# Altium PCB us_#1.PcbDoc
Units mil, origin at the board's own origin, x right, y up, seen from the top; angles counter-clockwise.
Board outline 1397.64 x 1968.5 mil, 2 copper layers (Top Layer, Bottom Layer); 23 components, 13 nets, 121 pads, 6 vias.
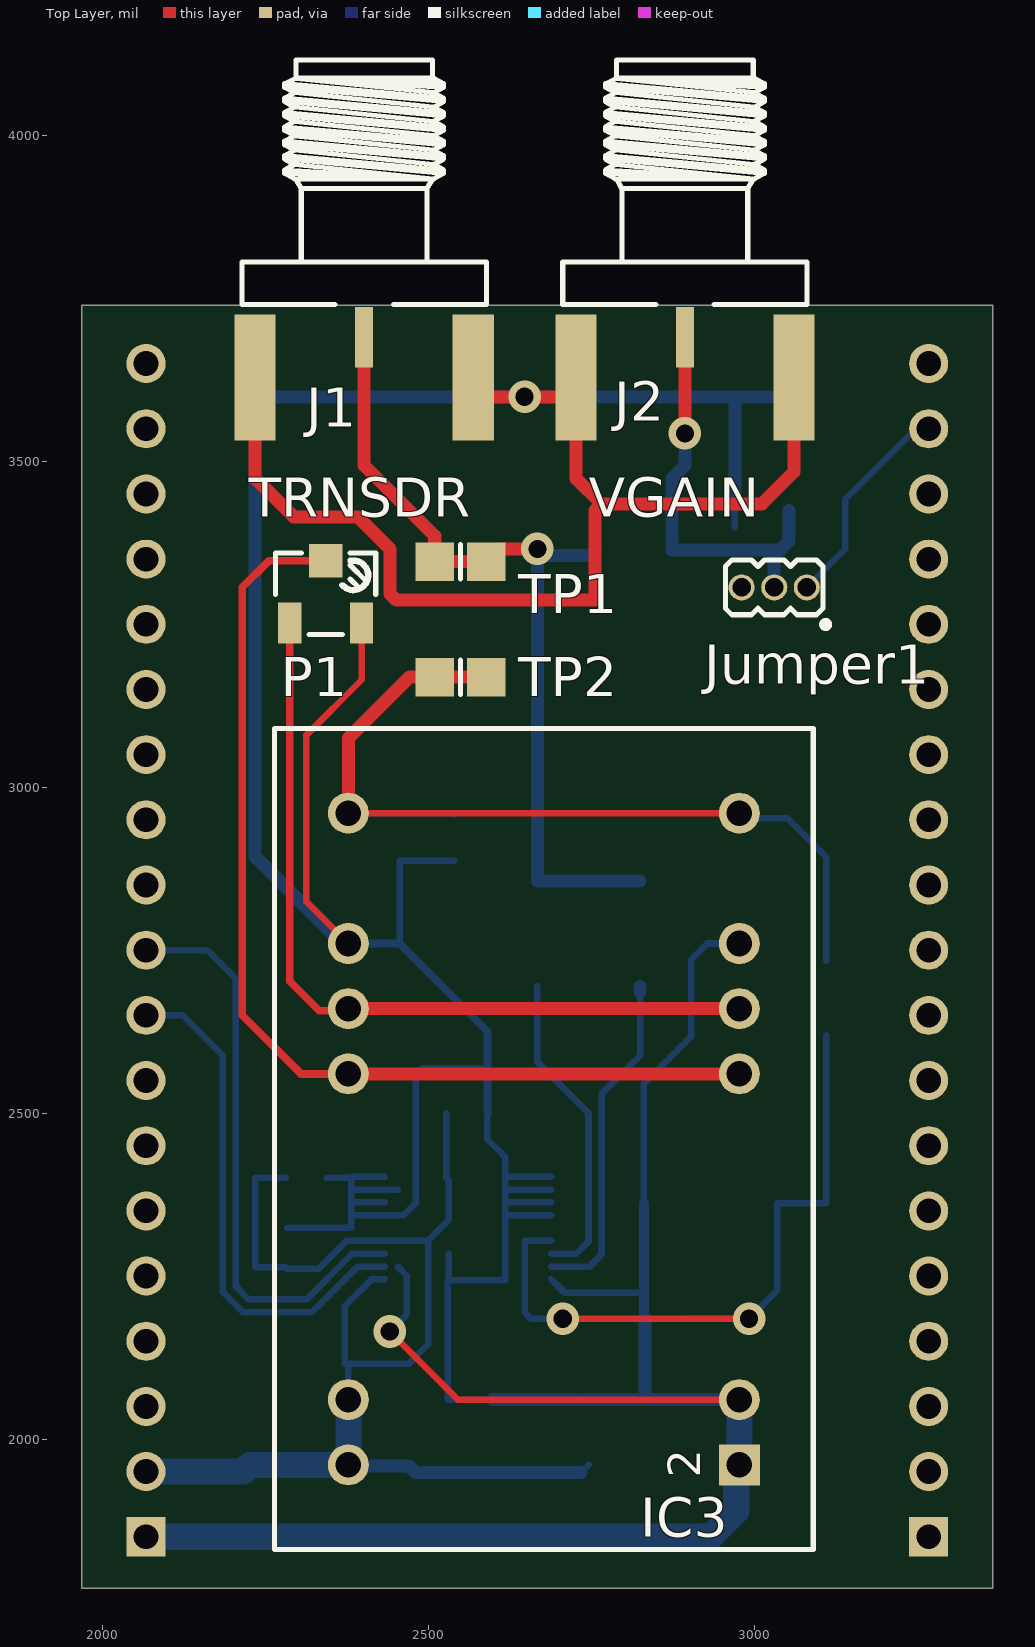
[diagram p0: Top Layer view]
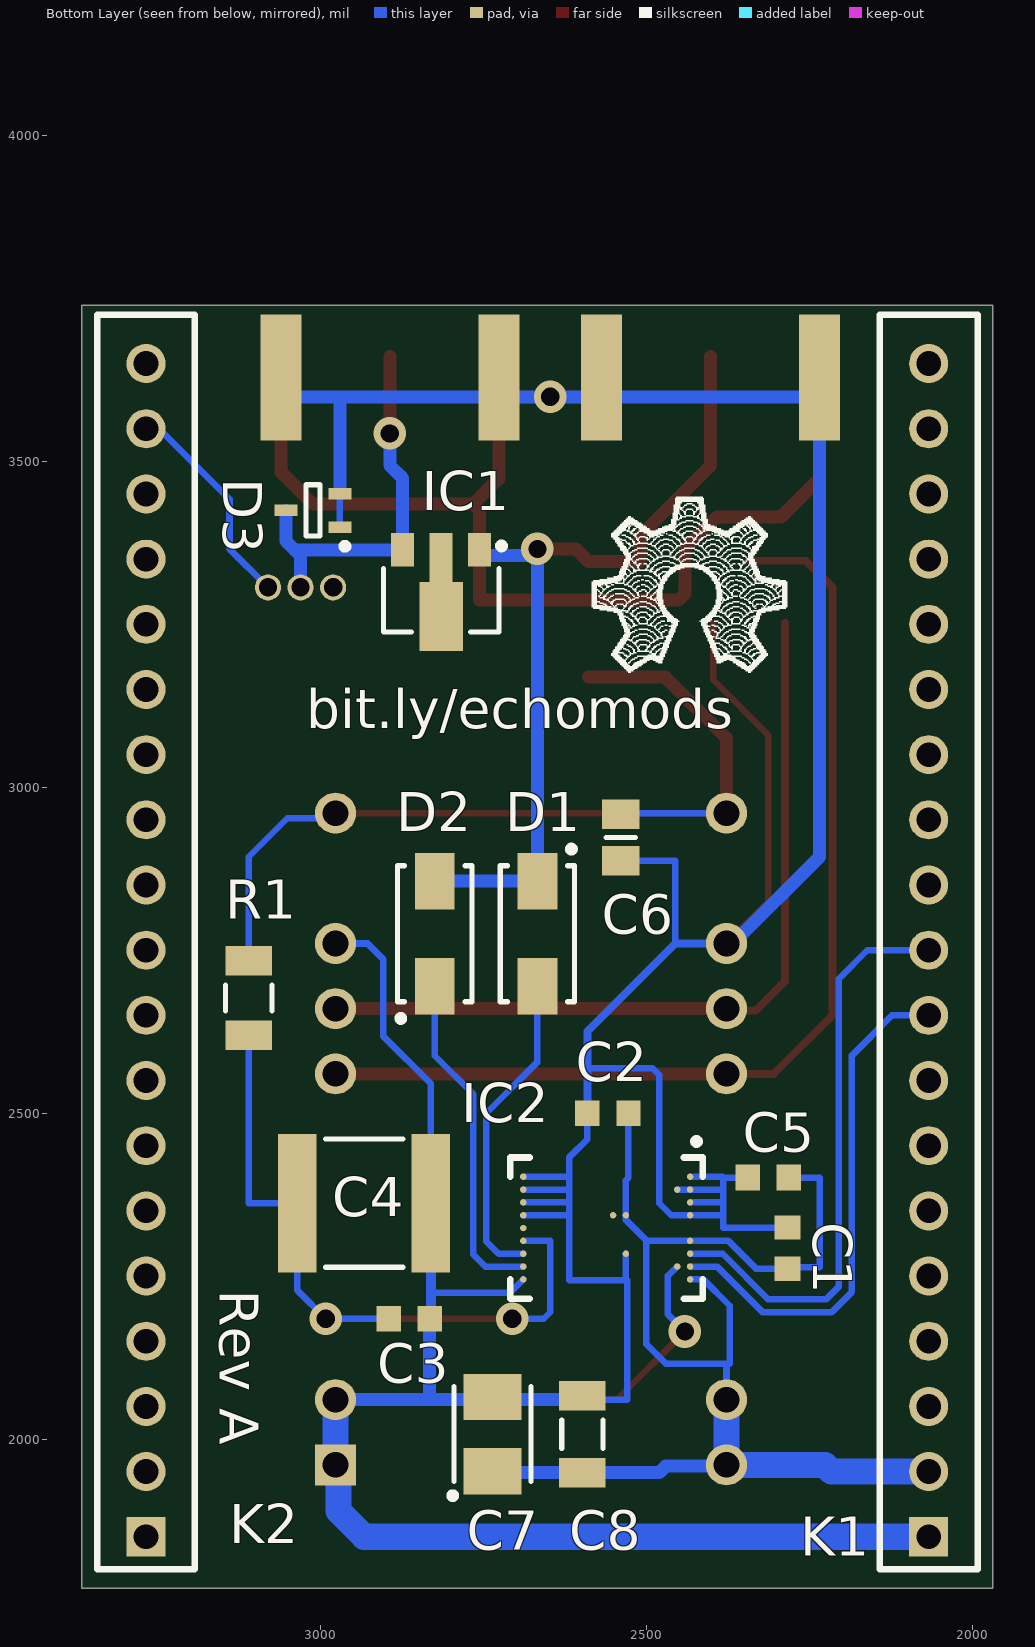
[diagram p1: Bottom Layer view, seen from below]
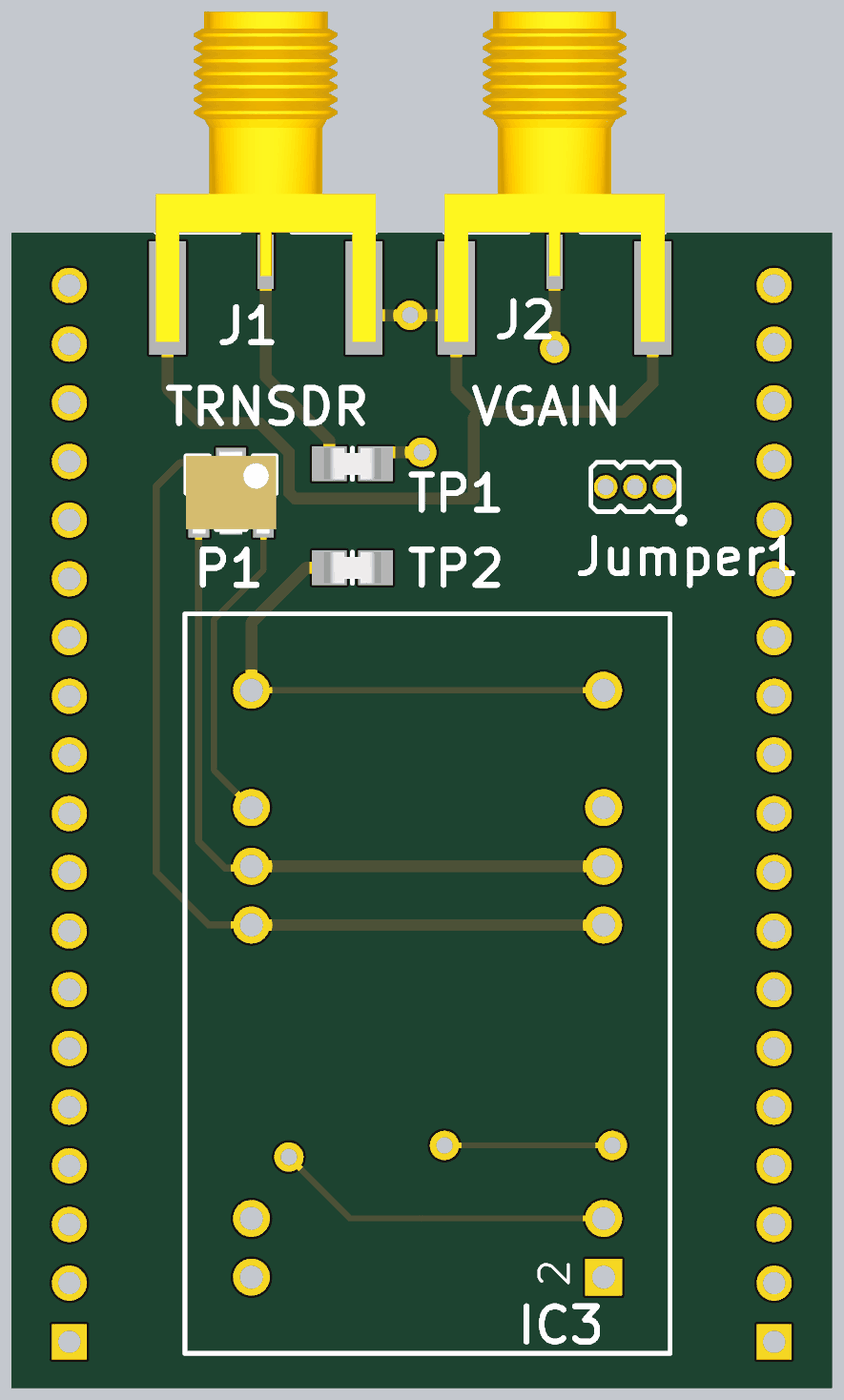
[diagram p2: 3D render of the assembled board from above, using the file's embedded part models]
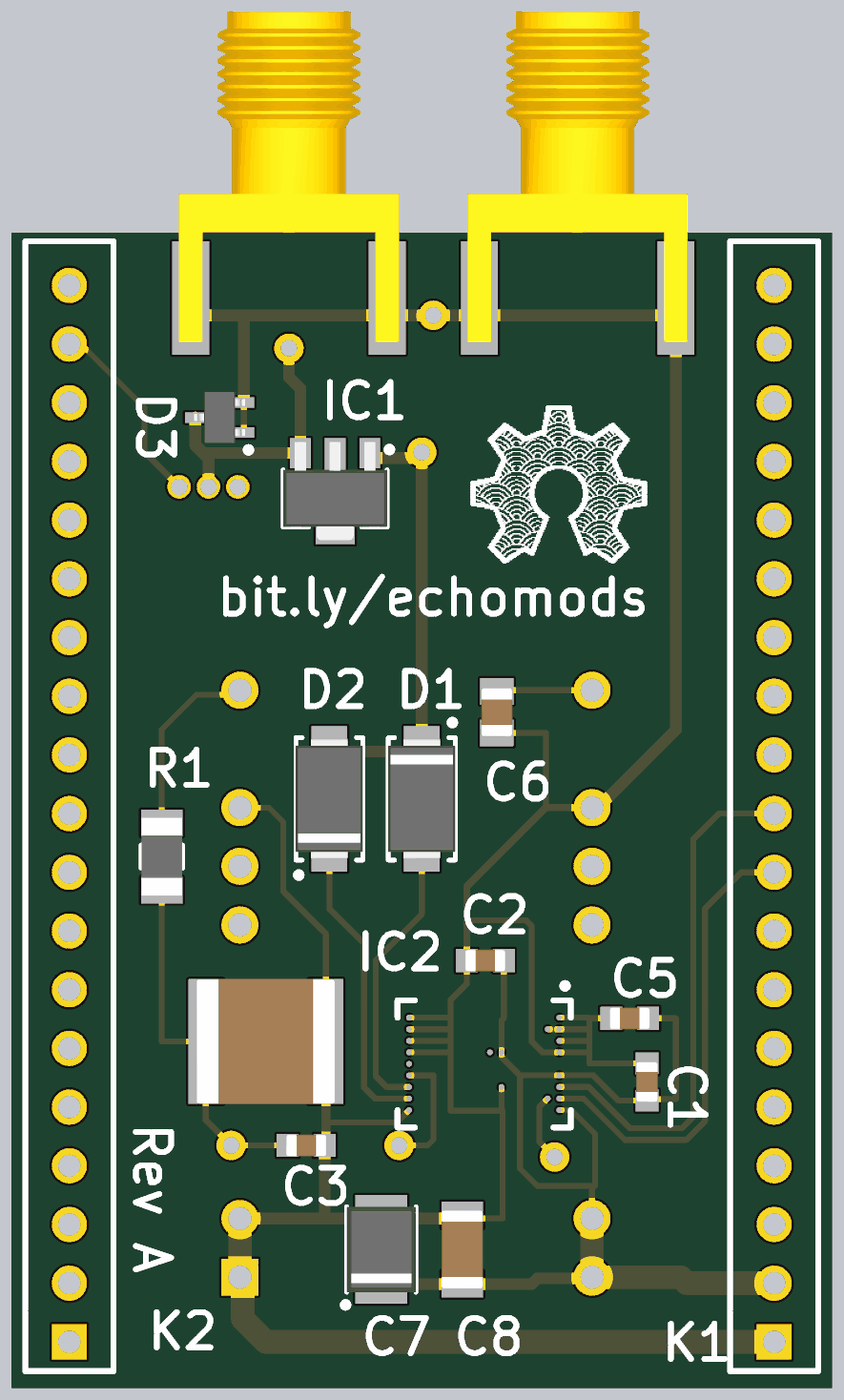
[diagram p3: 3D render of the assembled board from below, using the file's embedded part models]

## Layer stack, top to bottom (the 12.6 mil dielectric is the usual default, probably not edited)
Top Layer: signal copper 1.4
Dielectric: dielectric 12.6, FR-4, Dk 4.8
Bottom Layer: signal copper 1.4

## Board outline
1968.5,1771.65 3366.14,1771.65 3366.14,3740.16 1968.5,3740.16

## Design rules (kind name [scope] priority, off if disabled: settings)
Clearance [All] p1: gap=7
PolygonConnect [All] p1: connectstyle=Relief reliefconductorwidth=10 reliefentries=4 polygonreliefangle="90 Angle" airgapwidth=10
RoutingVias [All] p1: holewidth=28 width=50 viastyle="Through Hole" minholewidth=28 minwidth=50 maxholewidth=28 maxwidth=50
SolderMaskExpansion [All] p1: expansion=4
Width [All] p1: maxlimit=40 minlimit=10 preferedwidth=10 minimp=50.000000 maximp=50.000000 favimp=50.000000
28 further rules are at their usual default settings.

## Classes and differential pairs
net class RF: NetD1_1 NetD3_3

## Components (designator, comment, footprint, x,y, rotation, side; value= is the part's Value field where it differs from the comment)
C1 "100nF" CAPC1608X87N 2283.46,2293.31 r270 bottom
C2 "100nF" CAPC1608X87N 2559.06,2500 r180 bottom
C3 "100nF" CAPC1608X87N 2864.17,2185.04 r0 bottom
C4 "1uF" CAPC5650X165N 2933.07,2362.2 r0 bottom
C5 "100nF" CAPC1608X87N 2312.99,2401.57 r180 bottom
C6 "4.7nF" CAPC2012X110N 2539.37,2923.23 r90 bottom
C7 "10uF" CAPMP3528X210N 2736.22,2007.87 r90 bottom
C8 "47uF" CAPC3216X180N 2598.43,2007.87 r270 bottom
D1 "ES1D" DIOM5027X244N 2667.32,2775.59 r270 bottom
D2 "ES1D" DIOM5027X244N 2824.8,2775.59 r90 bottom
D3 "BAT64-04W" SOT65P210X100-3N 3011.81,3425.2 r0 bottom
IC1 "MD0100N8-G" SOT89 2814.96,3287.4 r270 bottom
IC2 "HV7360LA-G" BGA22C50P9X14_500X700X105 2561,2324 r270 bottom
IC3 "R05-100B" PWS_RECOM_R05-100B 2677.17,2460.63 r90 top
J1 "SMA" AMPHENOL_132357-11 2401.57,3690.94 r270 top
J2 "SMA" AMPHENOL_132357-11 2893.7,3690.94 r270 top
Jumper1 "Family" SULLINS_GRPB031VWVN 3080.71,3307.09 r180 top
K1 "PLS_2.54mm-19" PLS_2.54mm-19 2066.93,1850.39 r180 bottom
K2 "PLS_2.54mm-19" PLS_2.54mm-19 3267.72,1850.39 r180 bottom
P1 "5k" TRIM_BOURNS_3223W 2342.52,3297.24 r0 top
R1 "4k7" RESC3216X65N 3110.24,2677.17 r90 bottom
TP1 "Test Point" NICOMATIC_C12000B 2549.21,3346.46 r0 top
TP2 "Test Point" NICOMATIC_C12000B 2549.21,3169.29 r180 top

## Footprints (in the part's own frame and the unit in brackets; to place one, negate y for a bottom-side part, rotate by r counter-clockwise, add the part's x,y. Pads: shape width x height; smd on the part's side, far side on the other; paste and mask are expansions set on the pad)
AMPHENOL_132357-11 [mm]
  rect 2.35x0.7 smd: 1(0,0)
  rect 4.9x1.6 smd: 2(1.575,4.25) 2(1.575,-4.25)
  rect 4.9x1.6 smd far side: 2(1.575,4.25) 2(1.575,-4.25)
  silkscreen extent -10.81,-4.76 -1.28,4.76, body extent -10.8,-4.76 3.48,4.76, height 4.08
BGA22C50P9X14_500X700X105 [mm] "BGA, 22-Leads, Body 5.00x7.00mmx1.05mm, Pitch 0.50mm"
  round 0.25 smd: A1(-2,3.25) A2(-1.5,3.25) A3(-1,3.25) A4(-0.5,3.25) A6(0.5,3.25) A7(1,3.25) A8(1.5,3.25) A9(2,3.25) B2(-1.5,2.75) B8(1.5,2.75) F4(-0.5,0.75) F7(1,0.75) G4(-0.5,0.25) P1(-2,-3.25) P2(-1.5,-3.25) P3(-1,-3.25) P4(-0.5,-3.25) P5(0,-3.25) P6(0.5,-3.25) P7(1,-3.25) P8(1.5,-3.25) P9(2,-3.25)
  silkscreen extent -3.5,-3.75 2.75,3.75
CAPC1608X87N [mm]
  rect 0.95x1 smd: 1(-0.8,0) 2(0.8,0)
  body extent -0.87,-0.47 0.88,0.48, height 0.87
CAPC2012X110N [mm]
  rect 1.15x1.45 smd: 1(-0.9,0) 2(0.9,0)
  silkscreen extent 0,-0.58 0,0.58, body extent -1.05,-0.67 1.05,0.68, height 1.1
CAPC3216X180N [mm]
  rect 1.15x1.8 smd: 1(-1.5,0) 2(1.5,0)
  silkscreen extent -0.55,-0.8 0.55,0.8, body extent -1.7,-0.9 1.7,0.9, height 1.8
CAPC5650X165N [mm]
  rect 1.5x5.4 smd: 1(-2.6,0) 2(2.6,0)
  silkscreen extent -1.5,-2.5 1.5,2.5, body extent -3,-2.7 3,2.7, height 1.65
CAPMP3528X210N [mm]
  rect 1.8x2.25 smd: 1(-1.45,0) 2(1.45,0)
  silkscreen extent -2.52,-1.5 1.85,1.68, body extent -1.85,-1.5 1.85,1.5, height 2.1
DIOM5027X244N [mm]
  rect 2.2x1.55 smd: 1(-2.05,0) 2(2.05,0)
  silkscreen extent -3.42,-1.45 2.65,1.45, body extent -2.6,-1.45 2.6,1.45, height 2.44
NICOMATIC_C12000B [mm]
  rect 1.5x1.5 smd: 1(-1,0) 1(1,0)
  silkscreen extent 0,-0.67 0,0.67, body extent -1.25,-0.67 1.25,0.68, height 1.5
PLS_2.54mm-19 [mil] "soldering pads"
  rect 60x60 hole 38: 1(0,0)
  round 60 hole 38: 2(0,100) 3(0,200) 4(0,300) 5(0,400) 6(0,500) 7(0,600) 8(0,700) 9(0,800) 10(0,900) 11(0,1000) 12(0,1100) 13(0,1200) 14(0,1300) 15(0,1400) 16(0,1500) 17(0,1600) 18(0,1700) 19(0,1800)
  silkscreen extent -75,-50 75,1875
PWS_RECOM_R05-100B [mm]
  rect 1.6x1.6 hole 1: 2(-12.7,-7.62)
  round 1.6 hole 1: 3(-10.16,-7.62) 8(2.54,-7.62) 9(5.08,-7.62) 10(7.62,-7.62) 12(12.7,-7.62) 13(12.7,7.62) 15(7.62,7.62) 16(5.08,7.62) 17(2.54,7.62) 22(-10.16,7.62) 23(-12.7,7.62)
  silkscreen extent -16,-10.5 16,10.5, body extent -16,-10.5 16,10.5, height 9.4
RESC3216X65N [mm]
  rect 1.15x1.8 smd: 1(-1.45,0) 2(1.45,0)
  silkscreen extent -0.5,-0.9 0.5,0.9, body extent -1.67,-0.87 1.68,0.88, height 0.65
SOT65P210X100-3N [mm]
  rect 0.9x0.45 smd: 1(-1.05,0.65) 2(-1.05,-0.65) 3(1.05,0)
  silkscreen extent -1.37,-1 0.28,1.52, body extent -1.1,-1.1 1.1,1.1, height 1
SOT89 [mm]
  rect 1.3x0.9 smd: 1(-1.965,1.5) 3(-1.965,-1.5)
  rect 1.9x0.9 smd: 2(-1.665,0)
  rect 2.7x1.7 smd: 2(0.635,0)
  silkscreen extent -2.24,-2.25 1.24,2.47, body extent -2.44,-2.25 1.81,2.25, height 1.6
SULLINS_GRPB031VWVN [mil]
  round 40 hole 28: 1(0,0) 2(50,0) 3(100,0)
  silkscreen extent -33,-42 125,61
TRIM_BOURNS_3223W [mm]
  rect 0.9x1.6 smd: 1(-1.4,-1.14) 3(1.4,-1.14)
  rect 1.3x1.3 smd: 2(0,1.29)
  silkscreen extent -1.95,-1.59 1.95,1.59, body extent -1.95,-1.81 1.95,1.81, height 4.16

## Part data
C1 C2 C3 C5: library part CC0603_100NF_50V_10%_X7R, "Non-polarised capacitor"
C4: library part CC2220_1UF_200V_10%_X7R, "Non-polarised capacitor"
C6: library part CC0805_4.7NF_250V_10%_X7R, "Non-polarised capacitor"
C7: library part CTE3528-21_10UF_16V_10%_LESR0800, "Polarised capacitor"
C8: library part CC1206_47UF_25V_20%_X5R, "Non-polarised capacitor"
D1 D2: "Diode"
D3: "Serial Diode"
IC1: "3-Ultra-Sound HV Switch 1=A 2=COM 3=B"
IC3: "Power Supply"
J1 J2: library part AMPHENOL_132357-11
Jumper1: library part "Connector 3 Male", "Connector 3 Male"
P1: library part TRIM_11T_5K_BOURNS_3223W-1-502E, "Trimming Potentiometer"
R1: library part R1206_4K7_1%_0.25W_100PPM, "Resistor - 1%"
TP1 TP2: library part NICOMATIC_C12000B

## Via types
v1: diameter 50, hole 28, Top Layer to Bottom Layer, 6 vias

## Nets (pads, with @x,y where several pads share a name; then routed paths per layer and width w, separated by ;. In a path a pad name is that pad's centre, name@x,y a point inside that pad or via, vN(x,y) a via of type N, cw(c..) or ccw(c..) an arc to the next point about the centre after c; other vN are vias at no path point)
AGND: C1.1 C2.1 C3.1 C4.1 C5.1 C6.1 C7.2 C8.1 D3.1 D3.2 IC2.A1 IC2.A2 IC2.A3 IC2.A4 IC2.B2 IC2.B8 IC2.F7 IC2.P1 IC2.P2 IC2.P3 IC2.P4 IC2.P9 IC3.2 IC3.3 IC3.10 IC3.15 J1.2 J2.2 K1.1 P1.3 | length 9622.3
  Top Layer w10: IC3.15 2312.99,2824.8 2312.99,3080.71 2397.64,3165.35 P1.3 ; v1(2440.94,2165.35) 2545.67,2060.63 IC3.3
  Top Layer w20: J1.2@2234.25,3628.94 2234.25,3474.41 2293.31,3415.35 2391.73,3415.35 2440.94,3366.14 2440.94,3297.24 2450.79,3287.4 2755.91,3287.4 2755.91,3425.2 2765.75,3435.04 ; J1.2@2568.9,3599.41 2726.38,3599.41 2726.38,3474.41 2765.75,3435.04 ; J2.2@3061.02,3599.41 3061.02,3484.25 3011.81,3435.04 2765.75,3435.04
  Bottom Layer w10: C1.1 2381.89,2324.8 2381.89,2342.52 2381.89,2362.2 ; C5.1 2381.89,2401.57 2381.89,2363.37 ; 2381.94,2383.06 IC2.A2 IC2.B2 ; 2383.06,2343.68 IC2.A4 2461.8,2343.68 2480.32,2362.2 2480.32,2559.06 2490.16,2568.9 2590.55,2568.9 ; 2383.06,2363.37 IC2.A3 ; 2383.06,2402.74 IC2.A1 ; v1(2440.94,2165.35) 2467,2191.41 2467,2250.68 IC2.B8 ; 2455.91,2760.63 2455.91,2887.8 C6.1 ; IC2.F7 2531.47,2246.04 2529.53,2244.09 ; C2.1 2590.55,2460.45 2618.11,2432.89 2618.11,2383.06 ; C8.1@2598.43,2060.63 2529.53,2060.63 2529.53,2244.09 ; 2618.37,2402.74 IC2.P1 ; IC2.P9 2709.8,2224.41 2830.71,2224.41 ; IC2.P4 2618.11,2343.68 ; IC2.P3 2618.11,2363.37 ; IC2.P2 2618.11,2383.06 ; C3.1@2830.71,2187.01 C3.1 ; C4.1 2830.71,2545.28 2903.54,2618.11 2903.54,2736.22 2927.95,2760.63 IC3.10 ; D3.1 D3.2 ; 2529.53,2244.09 2618.11,2244.09 2618.11,2343.68 ; 2618.11,2343.68 2618.11,2363.37 ; 2618.11,2363.37 2618.11,2383.06
  Bottom Layer w12: IC3.15 2455.91,2760.63 2590.55,2625.98 2590.55,2568.9 C2.1
  Bottom Layer w15: C3.1@2830.71,2187.01 2830.71,2224.41 C4.1
  Bottom Layer w20: IC3.15@2367.32,2760.63 2234.25,2893.7 2234.25,3599.41 2970.47,3599.41 ; C8.1@2598.43,2060.63 C7.2@2731.89,2060.63 ; C7.2@2740.55,2060.63 IC3.3 ; 2832.68,2064.96 C3.1 ; D3.2 2970.47,3599.41 ; J2.2@3061.02,3599.41 2970.47,3599.41
  Bottom Layer w40: K1.1 2933.07,1850.39 2972.44,1889.76 2972.44,1955.91 IC3.2 IC3.3
  other v1: 2647.64,3599.41
HVOUT: C6.2 IC3.12 IC3.13 R1.2 TP2.1 | length 1448.5
  Top Layer w10: IC3.13 IC3.12
  Top Layer w20: IC3.13 2377.17,3075.59 2470.87,3169.29 2509.84,3169.29 TP2.1@2588.58,3169.29
  Bottom Layer w10: IC3.13 2537.4,2960.63 C6.2 ; IC3.12 2985.04,2952.76 3051.18,2952.76 3110.24,2893.7 R1.2
NetC3_2: C3.2 C4.2 IC2.P6 R1.1 | length 1123.6
  Top Layer w10: v1(2706.06,2185.04) v1(2992.13,2185.04)
  Bottom Layer w10: IC2.P6 2647.64,2304.32 2647.64,2194.88 2657.48,2185.04 v1(2706.06,2185.04) ; C3.2 v1(2992.13,2185.04) 3035.43,2228.35 C4.2 3110.24,2362.2 R1.1
NetD1_1: D1.1 D2.2 IC1.1 J1.1 TP1.1 | length 1275
  Top Layer w20: J1.1@2401.57,3661.42 2401.57,3494.09 2509.84,3385.83 2509.84,3346.46 2588.58,3346.46 2608.27,3366.14 v1(2667.32,3366.14)
  Bottom Layer w20: IC1.1 2747.44,3356.3 2667.32,3356.3 D1.1 D2.2
NetD1_2: D1.2 IC2.P7 | length 488.5
  Bottom Layer w10: D1.2 2667.32,2578.74 2745.75,2500.32 2745.75,2303.46 2726.91,2284.63 IC2.P7
NetD2_1: D2.1 IC2.P8 | length 520.3
  Bottom Layer w10: IC2.P8 2747.23,2264.94 2765.75,2283.46 2765.75,2529.53 2824.8,2588.58 D2.1@2824.8,2687.01
  Bottom Layer w20: D2.1@2824.8,2687.01 D2.1
NetD3_3: D3.3 IC1.3 J2.1 Jumper1.2 | length 598.2
  Top Layer w20: v1(2893.7,3543.31) J2.1@2893.7,3661.42
  Bottom Layer w20: v1(2893.7,3543.31) 2893.7,3494.09 2874.02,3474.41 IC1.3 3039.96,3364.76 ; Jumper1.2 3030.71,3355.51 3039.96,3364.76 ; D3.3 3053.15,3377.95 3039.96,3364.76
NetIC3_8: IC3.8 IC3.17 P1.2 | length 1601.2
  Top Layer w12: P1.2 2255.51,3348.03 2214.57,3307.09 2214.57,2650.79 2304.72,2560.63 IC3.17
  Top Layer w20: IC3.17 IC3.8
NetIC3_9: IC3.9 IC3.16 P1.1 | length 1259.4
  Top Layer w12: P1.1 2287.4,2702.76 2332.68,2657.48 2374.02,2657.48 IC3.16
  Top Layer w20: IC3.16 IC3.9
PULSE_A: IC2.A8 K1.9 | length 796.7
  Bottom Layer w10: K1.9 2123.23,2650.39 2184.72,2588.9 2184.72,2225.97 2216.13,2194.57 2321.28,2194.57 2391.65,2264.94 IC2.A8
PULSE_B: IC2.A7 K1.10 | length 893.8
  Bottom Layer w10: K1.10 2161.02,2750.39 2204.72,2706.69 2204.72,2234.25 2224.41,2214.57 2312.99,2214.57 2383.06,2284.63 IC2.A7
VDD_5V: C1.2 C2.2 C5.2 C7.1 C8.2 IC2.A6 IC2.A9 IC2.F4 IC3.22 IC3.23 K1.2 | length 1985
  Top Layer w40: K1.2 K1.2@2068.5,1948.82
  Bottom Layer w10: C5.2 2234.25,2401.57 2234.25,2263.78 2281.5,2263.78 C1.2 2331.95,2261.81 2374.9,2304.76 2500,2304.76 ; 2372.05,2116.14 2372.05,2204.72 2412.58,2245.26 IC2.A9 ; IC3.22 2377.17,2111.02 ; 2377.17,2116.14 2470.47,2116.14 2500,2145.67 2500,2304.76 ; C2.2 2527.56,2401.44 2531.47,2397.53 IC2.F4 2531.47,2336.24 2500,2304.76 ; C7.1@2734.25,1948.82 C7.1 C7.1@2746.06,1960.63
  Bottom Layer w20: IC3.23@2379.13,1958.66 2470.47,1958.66 2480.31,1948.82 C8.2 C7.1@2734.25,1948.82
  Bottom Layer w40: K1.2@2065.35,1948.82 K1.2 2216.14,1950.39 2226.38,1960.63 IC3.23 IC3.22
"VGA IN": Jumper1.1 K2.18 | length 312.6
  Bottom Layer w10: Jumper1.1 3139.76,3366.14 3139.76,3442.13 K2.18@3248.03,3550.39
pads on no net: IC1.2 IC2.G4 IC2.P5 Jumper1.3 K1.3 K1.4 K1.5 K1.6 K1.7 K1.8 K1.11 K1.12 K1.13 K1.14 K1.15 K1.16 K1.17 K1.18 K1.19 K2.1 K2.2 K2.3 K2.4 K2.5 K2.6 K2.7 K2.8 K2.9 K2.10 K2.11 K2.12 K2.13 K2.14 K2.15 K2.16 K2.17 K2.19

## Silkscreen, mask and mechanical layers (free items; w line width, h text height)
Top Overlay:
  text "TRNSDR" at 2224.41,3415.35 h60
  text "VGAIN" at 2746.06,3415.35 h60
Bottom Overlay:
  drawing of 1520 lines, arcs and shapes, not listed
  text "bit.ly/echomods" at 3021.65,3090.55 h60
  text "Rev A" at 3155,2229 h60 r90
Mechanical 1:
  lines w10: 1968.5,1771.65 1968.5,3740.16 3366.14,3740.16 3366.14,3597.44 3366.14,3390.75 3366.14,3228.35 3366.14,2982.28 3366.14,2529.53 3366.14,2283.46 3366.14,2121.06 3366.14,1914.37 3366.14,1771.65 1968.5,1771.65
